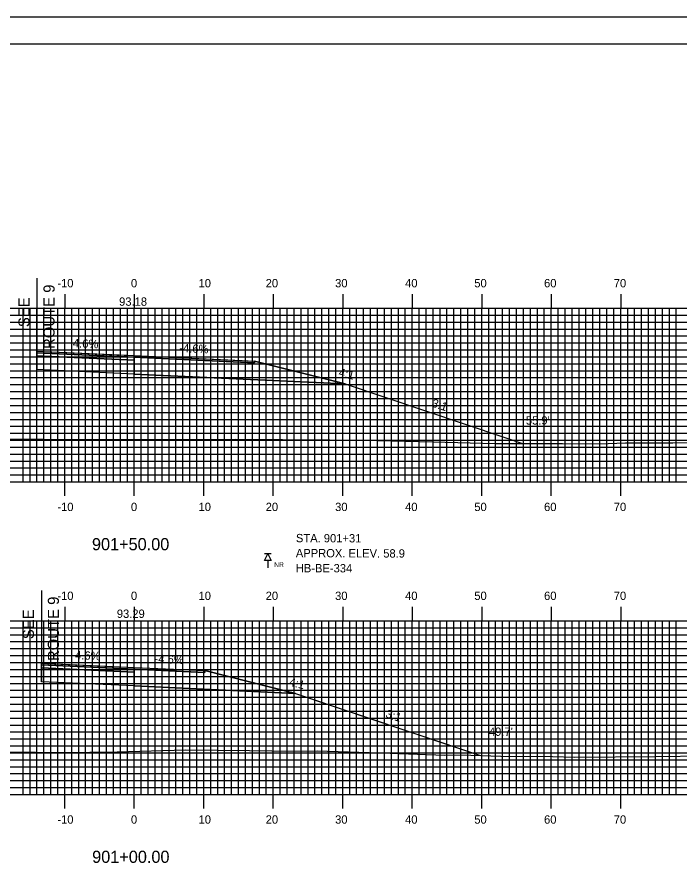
# Model space of a CAD drawing. Extents: x 856323 to 856666, y 364765 to 364985.
# Drawn here: x 856471.9 to 856567.3, y 364861.3 to 364985.2 of the extents above; entities that cross this region are included whole.
import ezdxf

# ---------------------------------------------------------------- set-up
doc = ezdxf.new("R2010")
doc.units = 0
for name, color, linetype in [('ANNOTATION', 7, 'Continuous'), ('BORDER', 7, 'Continuous'), ('BORING - NO REFUSAL', 7, 'Continuous'), ('D_Roadway_Centerline', 7, 'Continuous'), ('D_Roadway_Centerline_Text', 7, 'Continuous'), ('D_Roadway_Edge_Shoulder', 7, 'Continuous'), ('D_Roadway_Edge_TW', 7, 'Continuous'), ('D_Roadway_Pavement', 7, 'Continuous'), ('D_Roadway_SlopeLines', 7, 'Continuous'), ('D_Roadway_SubGrade', 7, 'Continuous'), ('D_Text_Standard', 7, 'Continuous'), ('H_V ANNOTATION', 7, 'Continuous'), ('MAJOR', 7, 'Continuous'), ('MINOR', 7, 'Continuous'), ('PLOT BOUNDARY', 7, 'Continuous'), ('S_Roadway_Centerline', 7, 'Continuous')]:
    doc.layers.add(name, color=color, linetype=linetype)

msp = doc.modelspace()

# ---------------------------------------------------------------- linework, layer by layer
at = {"layer": 'BORDER'}
msp.add_lwpolyline([(856339.17, 364771.3), (856659.17, 364771.3), (856659.17, 364981.3), (856339.17, 364981.3)], close=True, dxfattribs=at)
at = {"layer": 'BORING - NO REFUSAL'}
for p, q in [((856508.45, 364907.96), (856507.49, 364907.96)), ((856507.97, 364907), (856507.97, 364905.94))]:
    msp.add_line(p, q, dxfattribs=at)
msp.add_lwpolyline([(856507.97, 364907.96), (856508.45, 364907), (856507.49, 364907)], close=True, dxfattribs=at)
at = {"layer": 'D_Roadway_Centerline'}
for points in [[(856474.77, 364937.13), (856487.33, 364936.55), (856488.77, 364936.48), (856504.31, 364935.77), (856506.05, 364935.69), (856516.85, 364932.99), (856518.05, 364932.69), (856519.01, 364932.45), (856519.12, 364932.42), (856542.07, 364924.69), (856544.62, 364923.83)], [(856475.4, 364892.21), (856478.19, 364892.08), (856488.77, 364891.59), (856493.27, 364891.39), (856498.91, 364891.13), (856504.25, 364889.79), (856510.91, 364888.13), (856511.39, 364888.01), (856511.99, 364887.86), (856523.83, 364883.87), (856538.47, 364878.94)]]:
    msp.add_lwpolyline(points, dxfattribs=at)
at = {"layer": 'D_Roadway_Edge_Shoulder'}
for points in [[(856488.77, 364936.48), (856506.05, 364935.69), (856506.05, 364935.44), (856488.77, 364936.23)], [(856488.77, 364891.59), (856498.91, 364891.13), (856498.91, 364890.88), (856488.77, 364891.34)]]:
    msp.add_lwpolyline(points, close=True, dxfattribs=at)
at = {"layer": 'D_Roadway_Edge_TW'}
for points in [[(856474.77, 364937.13), (856488.77, 364936.48), (856488.77, 364936.23), (856474.77, 364936.88)], [(856474.77, 364937.13), (856488.77, 364936.48), (856488.77, 364936.23), (856474.77, 364936.88)], [(856474.77, 364937.13), (856488.77, 364936.48), (856488.77, 364936.23), (856474.77, 364936.88)], [(856475.4, 364892.21), (856488.77, 364891.59), (856488.77, 364891.34), (856475.4, 364891.96)], [(856475.4, 364892.21), (856488.77, 364891.59), (856488.77, 364891.34), (856475.4, 364891.96)]]:
    msp.add_lwpolyline(points, close=True, dxfattribs=at)
for points in [[(856474.77, 364937.13), (856474.77, 364936.88)], [(856474.77, 364937.13), (856474.77, 364936.88)], [(856475.4, 364892.21), (856475.4, 364891.96)], [(856475.4, 364892.21), (856475.4, 364891.96)], [(856475.4, 364892.21), (856488.77, 364891.59), (856488.77, 364891.34), (856475.4, 364891.96)]]:
    msp.add_lwpolyline(points, dxfattribs=at)
at = {"layer": 'D_Roadway_Pavement'}
for points in [[(856474.77, 364936.88), (856488.77, 364936.23), (856488.77, 364935.82), (856474.77, 364936.46)], [(856474.77, 364936.88), (856488.77, 364936.23), (856488.77, 364935.82), (856474.77, 364936.46)], [(856474.77, 364936.88), (856488.77, 364936.23), (856488.77, 364935.82), (856474.77, 364936.46)], [(856474.77, 364936.88), (856488.77, 364936.23), (856488.77, 364935.82), (856474.77, 364936.46)], [(856475.4, 364891.96), (856488.77, 364891.34), (856488.77, 364890.93), (856475.4, 364891.54)], [(856475.4, 364891.96), (856488.77, 364891.34), (856488.77, 364890.93), (856475.4, 364891.54)], [(856475.4, 364891.96), (856488.77, 364891.34), (856488.77, 364890.93), (856475.4, 364891.54)], [(856475.4, 364891.96), (856488.77, 364891.34), (856488.77, 364890.93), (856475.4, 364891.54)]]:
    msp.add_lwpolyline(points, close=True, dxfattribs=at)
for points in [[(856474.77, 364936.88), (856474.77, 364936.46)], [(856474.77, 364936.88), (856474.77, 364936.46)], [(856474.77, 364936.88), (856474.77, 364936.46)], [(856474.77, 364936.88), (856474.77, 364936.46)], [(856488.77, 364936.23), (856488.77, 364935.82)], [(856488.77, 364936.23), (856488.77, 364935.82)], [(856488.77, 364936.23), (856488.77, 364935.82)], [(856488.77, 364936.23), (856488.77, 364935.82)], [(856488.77, 364936.23), (856488.77, 364935.82)], [(856488.77, 364936.23), (856488.77, 364935.82)], [(856488.77, 364936.23), (856488.77, 364935.82)], [(856488.77, 364936.23), (856488.77, 364935.82)], [(856475.4, 364891.96), (856475.4, 364891.54)], [(856475.4, 364891.96), (856475.4, 364891.54)], [(856475.4, 364891.96), (856475.4, 364891.54)], [(856475.4, 364891.96), (856475.4, 364891.54)], [(856488.77, 364891.34), (856488.77, 364890.93)], [(856488.77, 364891.34), (856488.77, 364890.93)], [(856488.77, 364891.34), (856488.77, 364890.93)], [(856488.77, 364891.34), (856488.77, 364890.93)], [(856488.77, 364891.34), (856488.77, 364890.93)], [(856488.77, 364891.34), (856488.77, 364890.93)], [(856488.77, 364891.34), (856488.77, 364890.93)], [(856488.77, 364891.34), (856488.77, 364890.93)]]:
    msp.add_lwpolyline(points, dxfattribs=at)
at = {"layer": 'D_Roadway_SlopeLines'}
msp.add_lwpolyline([(856498.91, 364891.13), (856511.99, 364887.86), (856538.47, 364878.94)], dxfattribs=at)
at = {"layer": 'D_Roadway_SubGrade'}
for p, q in [((856474.77, 364947.6), (856474.77, 364934.46)), ((856475.4, 364902.68), (856475.4, 364889.54))]:
    msp.add_line(p, q, dxfattribs=at)
for points in [[(856474.77, 364936.46), (856488.77, 364935.82), (856488.77, 364933.82), (856474.77, 364934.46)], [(856474.77, 364936.46), (856488.77, 364935.82), (856488.77, 364933.82), (856474.77, 364934.46)], [(856488.77, 364935.82), (856488.77, 364936.23), (856506.05, 364935.44), (856506.05, 364935.69), (856519.12, 364932.42), (856488.77, 364933.82)], [(856488.77, 364933.82), (856519.12, 364932.42), (856506.05, 364935.69), (856506.05, 364935.44), (856488.77, 364936.23), (856488.77, 364935.82)], [(856488.77, 364935.82), (856488.77, 364936.23), (856506.05, 364935.44), (856506.05, 364935.69), (856519.12, 364932.42), (856488.77, 364933.82)], [(856475.4, 364891.54), (856488.77, 364890.93), (856488.77, 364888.93), (856475.4, 364889.54)], [(856475.4, 364891.54), (856488.77, 364890.93), (856488.77, 364888.93), (856475.4, 364889.54)], [(856488.77, 364890.93), (856488.77, 364891.34), (856498.91, 364890.88), (856498.91, 364891.13), (856511.99, 364887.86), (856488.77, 364888.93)], [(856488.77, 364888.93), (856511.99, 364887.86), (856498.91, 364891.13), (856498.91, 364890.88), (856488.77, 364891.34), (856488.77, 364890.93)], [(856488.77, 364890.93), (856488.77, 364891.34), (856498.91, 364890.88), (856498.91, 364891.13), (856511.99, 364887.86), (856488.77, 364888.93)]]:
    msp.add_lwpolyline(points, close=True, dxfattribs=at)
for points in [[(856474.77, 364936.46), (856474.77, 364934.46)], [(856474.77, 364936.46), (856474.77, 364934.46)], [(856475.4, 364891.54), (856475.4, 364889.54)], [(856475.4, 364891.54), (856475.4, 364889.54)]]:
    msp.add_lwpolyline(points, dxfattribs=at)
at = {"layer": 'MAJOR'}
for p, q in [((856478.77, 364945.31), (856478.77, 364943.3)), ((856488.77, 364945.31), (856488.77, 364943.3)), ((856498.77, 364945.31), (856498.77, 364943.3)), ((856508.77, 364945.31), (856508.77, 364943.3)), ((856518.77, 364945.31), (856518.77, 364943.3)), ((856528.77, 364945.31), (856528.77, 364943.3)), ((856538.77, 364945.31), (856538.77, 364943.3)), ((856548.77, 364945.31), (856548.77, 364943.3)), ((856558.77, 364945.31), (856558.77, 364943.3)), ((856348.77, 364943.3), (856628.77, 364943.3)), ((856348.77, 364943.3), (856628.77, 364943.3)), ((856478.77, 364918.3), (856478.77, 364943.3)), ((856488.77, 364918.3), (856488.77, 364943.3)), ((856498.77, 364918.3), (856498.77, 364943.3)), ((856508.77, 364918.3), (856508.77, 364943.3)), ((856518.77, 364918.3), (856518.77, 364943.3)), ((856528.77, 364918.3), (856528.77, 364943.3)), ((856538.77, 364918.3), (856538.77, 364943.3)), ((856548.77, 364918.3), (856548.77, 364943.3)), ((856558.77, 364918.3), (856558.77, 364943.3)), ((856348.77, 364938.3), (856628.77, 364938.3)), ((856348.77, 364933.3), (856628.77, 364933.3)), ((856348.77, 364928.3), (856628.77, 364928.3)), ((856348.77, 364923.3), (856628.77, 364923.3)), ((856348.77, 364918.3), (856628.77, 364918.3)), ((856348.77, 364918.3), (856628.77, 364918.3)), ((856478.77, 364916.3), (856478.77, 364918.3)), ((856488.77, 364916.3), (856488.77, 364918.3)), ((856498.77, 364916.3), (856498.77, 364918.3)), ((856508.77, 364916.3), (856508.77, 364918.3)), ((856518.77, 364916.3), (856518.77, 364918.3)), ((856528.77, 364916.3), (856528.77, 364918.3)), ((856538.77, 364916.3), (856538.77, 364918.3)), ((856548.77, 364916.3), (856548.77, 364918.3)), ((856558.77, 364916.3), (856558.77, 364918.3)), ((856478.77, 364900.31), (856478.77, 364898.3)), ((856488.77, 364900.31), (856488.77, 364898.3)), ((856498.77, 364900.31), (856498.77, 364898.3)), ((856508.77, 364900.31), (856508.77, 364898.3)), ((856518.77, 364900.31), (856518.77, 364898.3)), ((856528.77, 364900.31), (856528.77, 364898.3)), ((856538.77, 364900.31), (856538.77, 364898.3)), ((856548.77, 364900.31), (856548.77, 364898.3)), ((856558.77, 364900.31), (856558.77, 364898.3)), ((856348.77, 364898.3), (856628.77, 364898.3)), ((856348.77, 364898.3), (856628.77, 364898.3)), ((856478.77, 364873.3), (856478.77, 364898.3)), ((856488.77, 364873.3), (856488.77, 364898.3)), ((856498.77, 364873.3), (856498.77, 364898.3)), ((856508.77, 364873.3), (856508.77, 364898.3)), ((856518.77, 364873.3), (856518.77, 364898.3)), ((856528.77, 364873.3), (856528.77, 364898.3)), ((856538.77, 364873.3), (856538.77, 364898.3)), ((856548.77, 364873.3), (856548.77, 364898.3)), ((856558.77, 364873.3), (856558.77, 364898.3)), ((856348.77, 364893.3), (856628.77, 364893.3)), ((856348.77, 364888.3), (856628.77, 364888.3)), ((856348.77, 364883.3), (856628.77, 364883.3)), ((856348.77, 364878.3), (856628.77, 364878.3)), ((856348.77, 364873.3), (856628.77, 364873.3)), ((856348.77, 364873.3), (856628.77, 364873.3)), ((856478.77, 364871.3), (856478.77, 364873.3)), ((856488.77, 364871.3), (856488.77, 364873.3)), ((856498.77, 364871.3), (856498.77, 364873.3)), ((856508.77, 364871.3), (856508.77, 364873.3)), ((856518.77, 364871.3), (856518.77, 364873.3)), ((856528.77, 364871.3), (856528.77, 364873.3)), ((856538.77, 364871.3), (856538.77, 364873.3)), ((856548.77, 364871.3), (856548.77, 364873.3)), ((856558.77, 364871.3), (856558.77, 364873.3))]:
    msp.add_line(p, q, dxfattribs=at)
at = {"layer": 'MINOR'}
for p, q in [((856472.77, 364918.3), (856472.77, 364943.3)), ((856473.77, 364918.3), (856473.77, 364943.3)), ((856474.77, 364918.3), (856474.77, 364943.3)), ((856475.77, 364918.3), (856475.77, 364943.3)), ((856476.77, 364918.3), (856476.77, 364943.3)), ((856477.77, 364918.3), (856477.77, 364943.3)), ((856479.77, 364918.3), (856479.77, 364943.3)), ((856480.77, 364918.3), (856480.77, 364943.3)), ((856481.77, 364918.3), (856481.77, 364943.3)), ((856482.77, 364918.3), (856482.77, 364943.3)), ((856483.77, 364918.3), (856483.77, 364943.3)), ((856484.77, 364918.3), (856484.77, 364943.3)), ((856485.77, 364918.3), (856485.77, 364943.3)), ((856486.77, 364918.3), (856486.77, 364943.3)), ((856487.77, 364918.3), (856487.77, 364943.3)), ((856489.77, 364918.3), (856489.77, 364943.3)), ((856490.77, 364918.3), (856490.77, 364943.3)), ((856491.77, 364918.3), (856491.77, 364943.3)), ((856492.77, 364918.3), (856492.77, 364943.3)), ((856493.77, 364918.3), (856493.77, 364943.3)), ((856494.77, 364918.3), (856494.77, 364943.3)), ((856495.77, 364918.3), (856495.77, 364943.3)), ((856496.77, 364918.3), (856496.77, 364943.3)), ((856497.77, 364918.3), (856497.77, 364943.3)), ((856499.77, 364918.3), (856499.77, 364943.3)), ((856500.77, 364918.3), (856500.77, 364943.3)), ((856501.77, 364918.3), (856501.77, 364943.3)), ((856502.77, 364918.3), (856502.77, 364943.3)), ((856503.77, 364918.3), (856503.77, 364943.3)), ((856504.77, 364918.3), (856504.77, 364943.3)), ((856505.77, 364918.3), (856505.77, 364943.3)), ((856506.77, 364918.3), (856506.77, 364943.3)), ((856507.77, 364918.3), (856507.77, 364943.3)), ((856509.77, 364918.3), (856509.77, 364943.3)), ((856510.77, 364918.3), (856510.77, 364943.3)), ((856511.77, 364918.3), (856511.77, 364943.3)), ((856512.77, 364918.3), (856512.77, 364943.3)), ((856513.77, 364918.3), (856513.77, 364943.3)), ((856514.77, 364918.3), (856514.77, 364943.3)), ((856515.77, 364918.3), (856515.77, 364943.3)), ((856516.77, 364918.3), (856516.77, 364943.3)), ((856517.77, 364918.3), (856517.77, 364943.3)), ((856519.77, 364918.3), (856519.77, 364943.3)), ((856520.77, 364918.3), (856520.77, 364943.3)), ((856521.77, 364918.3), (856521.77, 364943.3)), ((856522.77, 364918.3), (856522.77, 364943.3)), ((856523.77, 364918.3), (856523.77, 364943.3)), ((856524.77, 364918.3), (856524.77, 364943.3)), ((856525.77, 364918.3), (856525.77, 364943.3)), ((856526.77, 364918.3), (856526.77, 364943.3)), ((856527.77, 364918.3), (856527.77, 364943.3)), ((856529.77, 364918.3), (856529.77, 364943.3)), ((856530.77, 364918.3), (856530.77, 364943.3)), ((856531.77, 364918.3), (856531.77, 364943.3)), ((856532.77, 364918.3), (856532.77, 364943.3)), ((856533.77, 364918.3), (856533.77, 364943.3)), ((856534.77, 364918.3), (856534.77, 364943.3)), ((856535.77, 364918.3), (856535.77, 364943.3)), ((856536.77, 364918.3), (856536.77, 364943.3)), ((856537.77, 364918.3), (856537.77, 364943.3)), ((856539.77, 364918.3), (856539.77, 364943.3)), ((856540.77, 364918.3), (856540.77, 364943.3)), ((856541.77, 364918.3), (856541.77, 364943.3)), ((856542.77, 364918.3), (856542.77, 364943.3)), ((856543.77, 364918.3), (856543.77, 364943.3)), ((856544.77, 364918.3), (856544.77, 364943.3)), ((856545.77, 364918.3), (856545.77, 364943.3)), ((856546.77, 364918.3), (856546.77, 364943.3)), ((856547.77, 364918.3), (856547.77, 364943.3)), ((856549.77, 364918.3), (856549.77, 364943.3)), ((856550.77, 364918.3), (856550.77, 364943.3)), ((856551.77, 364918.3), (856551.77, 364943.3)), ((856552.77, 364918.3), (856552.77, 364943.3)), ((856553.77, 364918.3), (856553.77, 364943.3)), ((856554.77, 364918.3), (856554.77, 364943.3)), ((856555.77, 364918.3), (856555.77, 364943.3)), ((856556.77, 364918.3), (856556.77, 364943.3)), ((856557.77, 364918.3), (856557.77, 364943.3)), ((856559.77, 364918.3), (856559.77, 364943.3)), ((856560.77, 364918.3), (856560.77, 364943.3)), ((856561.77, 364918.3), (856561.77, 364943.3)), ((856562.77, 364918.3), (856562.77, 364943.3)), ((856563.77, 364918.3), (856563.77, 364943.3)), ((856564.77, 364918.3), (856564.77, 364943.3)), ((856565.77, 364918.3), (856565.77, 364943.3)), ((856566.77, 364918.3), (856566.77, 364943.3)), ((856348.77, 364942.3), (856628.77, 364942.3)), ((856348.77, 364941.3), (856628.77, 364941.3)), ((856348.77, 364940.3), (856628.77, 364940.3)), ((856348.77, 364939.3), (856628.77, 364939.3)), ((856348.77, 364937.3), (856628.77, 364937.3)), ((856348.77, 364936.3), (856628.77, 364936.3)), ((856348.77, 364935.3), (856628.77, 364935.3)), ((856348.77, 364934.3), (856628.77, 364934.3)), ((856348.77, 364932.3), (856628.77, 364932.3)), ((856348.77, 364931.3), (856628.77, 364931.3)), ((856348.77, 364930.3), (856628.77, 364930.3)), ((856348.77, 364929.3), (856628.77, 364929.3)), ((856348.77, 364927.3), (856628.77, 364927.3)), ((856348.77, 364926.3), (856628.77, 364926.3)), ((856348.77, 364925.3), (856628.77, 364925.3)), ((856348.77, 364924.3), (856628.77, 364924.3)), ((856348.77, 364922.3), (856628.77, 364922.3)), ((856348.77, 364921.3), (856628.77, 364921.3)), ((856348.77, 364920.3), (856628.77, 364920.3)), ((856348.77, 364919.3), (856628.77, 364919.3)), ((856348.77, 364897.3), (856628.77, 364897.3)), ((856472.77, 364873.3), (856472.77, 364898.3)), ((856473.77, 364873.3), (856473.77, 364898.3)), ((856474.77, 364873.3), (856474.77, 364898.3)), ((856475.77, 364873.3), (856475.77, 364898.3)), ((856476.77, 364873.3), (856476.77, 364898.3)), ((856477.77, 364873.3), (856477.77, 364898.3)), ((856479.77, 364873.3), (856479.77, 364898.3)), ((856480.77, 364873.3), (856480.77, 364898.3)), ((856481.77, 364873.3), (856481.77, 364898.3)), ((856482.77, 364873.3), (856482.77, 364898.3)), ((856483.77, 364873.3), (856483.77, 364898.3)), ((856484.77, 364873.3), (856484.77, 364898.3)), ((856485.77, 364873.3), (856485.77, 364898.3)), ((856486.77, 364873.3), (856486.77, 364898.3)), ((856487.77, 364873.3), (856487.77, 364898.3)), ((856489.77, 364873.3), (856489.77, 364898.3)), ((856490.77, 364873.3), (856490.77, 364898.3)), ((856491.77, 364873.3), (856491.77, 364898.3)), ((856492.77, 364873.3), (856492.77, 364898.3)), ((856493.77, 364873.3), (856493.77, 364898.3)), ((856494.77, 364873.3), (856494.77, 364898.3)), ((856495.77, 364873.3), (856495.77, 364898.3)), ((856496.77, 364873.3), (856496.77, 364898.3)), ((856497.77, 364873.3), (856497.77, 364898.3)), ((856499.77, 364873.3), (856499.77, 364898.3)), ((856500.77, 364873.3), (856500.77, 364898.3)), ((856501.77, 364873.3), (856501.77, 364898.3)), ((856502.77, 364873.3), (856502.77, 364898.3)), ((856503.77, 364873.3), (856503.77, 364898.3)), ((856504.77, 364873.3), (856504.77, 364898.3)), ((856505.77, 364873.3), (856505.77, 364898.3)), ((856506.77, 364873.3), (856506.77, 364898.3)), ((856507.77, 364873.3), (856507.77, 364898.3)), ((856509.77, 364873.3), (856509.77, 364898.3)), ((856510.77, 364873.3), (856510.77, 364898.3)), ((856511.77, 364873.3), (856511.77, 364898.3)), ((856512.77, 364873.3), (856512.77, 364898.3)), ((856513.77, 364873.3), (856513.77, 364898.3)), ((856514.77, 364873.3), (856514.77, 364898.3)), ((856515.77, 364873.3), (856515.77, 364898.3)), ((856516.77, 364873.3), (856516.77, 364898.3)), ((856517.77, 364873.3), (856517.77, 364898.3)), ((856519.77, 364873.3), (856519.77, 364898.3)), ((856520.77, 364873.3), (856520.77, 364898.3)), ((856521.77, 364873.3), (856521.77, 364898.3)), ((856522.77, 364873.3), (856522.77, 364898.3)), ((856523.77, 364873.3), (856523.77, 364898.3)), ((856524.77, 364873.3), (856524.77, 364898.3)), ((856525.77, 364873.3), (856525.77, 364898.3)), ((856526.77, 364873.3), (856526.77, 364898.3)), ((856527.77, 364873.3), (856527.77, 364898.3)), ((856529.77, 364873.3), (856529.77, 364898.3)), ((856530.77, 364873.3), (856530.77, 364898.3)), ((856531.77, 364873.3), (856531.77, 364898.3)), ((856532.77, 364873.3), (856532.77, 364898.3)), ((856533.77, 364873.3), (856533.77, 364898.3)), ((856534.77, 364873.3), (856534.77, 364898.3)), ((856535.77, 364873.3), (856535.77, 364898.3)), ((856536.77, 364873.3), (856536.77, 364898.3)), ((856537.77, 364873.3), (856537.77, 364898.3)), ((856539.77, 364873.3), (856539.77, 364898.3)), ((856540.77, 364873.3), (856540.77, 364898.3)), ((856541.77, 364873.3), (856541.77, 364898.3)), ((856542.77, 364873.3), (856542.77, 364898.3)), ((856543.77, 364873.3), (856543.77, 364898.3)), ((856544.77, 364873.3), (856544.77, 364898.3)), ((856545.77, 364873.3), (856545.77, 364898.3)), ((856546.77, 364873.3), (856546.77, 364898.3)), ((856547.77, 364873.3), (856547.77, 364898.3)), ((856549.77, 364873.3), (856549.77, 364898.3)), ((856550.77, 364873.3), (856550.77, 364898.3)), ((856551.77, 364873.3), (856551.77, 364898.3)), ((856552.77, 364873.3), (856552.77, 364898.3)), ((856553.77, 364873.3), (856553.77, 364898.3)), ((856554.77, 364873.3), (856554.77, 364898.3)), ((856555.77, 364873.3), (856555.77, 364898.3)), ((856556.77, 364873.3), (856556.77, 364898.3)), ((856557.77, 364873.3), (856557.77, 364898.3)), ((856559.77, 364873.3), (856559.77, 364898.3)), ((856560.77, 364873.3), (856560.77, 364898.3)), ((856561.77, 364873.3), (856561.77, 364898.3)), ((856562.77, 364873.3), (856562.77, 364898.3)), ((856563.77, 364873.3), (856563.77, 364898.3)), ((856564.77, 364873.3), (856564.77, 364898.3)), ((856565.77, 364873.3), (856565.77, 364898.3)), ((856566.77, 364873.3), (856566.77, 364898.3)), ((856348.77, 364896.3), (856628.77, 364896.3)), ((856348.77, 364895.3), (856628.77, 364895.3)), ((856348.77, 364894.3), (856628.77, 364894.3)), ((856348.77, 364892.3), (856628.77, 364892.3)), ((856348.77, 364891.3), (856628.77, 364891.3)), ((856348.77, 364890.3), (856628.77, 364890.3)), ((856348.77, 364889.3), (856628.77, 364889.3)), ((856348.77, 364887.3), (856628.77, 364887.3)), ((856348.77, 364886.3), (856628.77, 364886.3)), ((856348.77, 364885.3), (856628.77, 364885.3)), ((856348.77, 364884.3), (856628.77, 364884.3)), ((856348.77, 364882.3), (856628.77, 364882.3)), ((856348.77, 364881.3), (856628.77, 364881.3)), ((856348.77, 364880.3), (856628.77, 364880.3)), ((856348.77, 364879.3), (856628.77, 364879.3)), ((856348.77, 364877.3), (856628.77, 364877.3)), ((856348.77, 364876.3), (856628.77, 364876.3)), ((856348.77, 364875.3), (856628.77, 364875.3)), ((856348.77, 364874.3), (856628.77, 364874.3))]:
    msp.add_line(p, q, dxfattribs=at)
at = {"layer": 'PLOT BOUNDARY'}
msp.add_lwpolyline([(856322.98, 364765.18), (856662.98, 364765.18), (856662.98, 364985.18), (856322.98, 364985.18)], close=True, dxfattribs=at)
at = {"layer": 'S_Roadway_Centerline'}
for points in [[(856469.99, 364924.48), (856481.66, 364924.38), (856483.59, 364924.39), (856484.17, 364924.38), (856486.38, 364924.39), (856503.32, 364924.46), (856516.92, 364924.34), (856521.76, 364924.3), (856531.69, 364924.06), (856540.75, 364923.82), (856544.17, 364923.83), (856550.39, 364923.82), (856555.71, 364923.79), (856559.44, 364923.93), (856566.27, 364923.94), (856576.82, 364924.1), (856581.11, 364923.92), (856590.28, 364924.07), (856594.86, 364924.09), (856605.52, 364923.7), (856614.14, 364923.57), (856622.01, 364923.48), (856628.77, 364923.69)], [(856470.76, 364879.44), (856478.38, 364879.33), (856486.33, 364879.45), (856496.15, 364879.71), (856505.33, 364879.61), (856511.77, 364879.53), (856515.07, 364879.59), (856525.6, 364879.25), (856533.48, 364878.95), (856535.78, 364879.03), (856541.53, 364878.84), (856548.97, 364878.79), (856552.15, 364878.69), (856563.84, 364878.75), (856570.89, 364878.85)]]:
    msp.add_lwpolyline(points, dxfattribs=at)

# ---------------------------------------------------------------- texts
at = {"layer": 'ANNOTATION'}
for s, height, rotation, p in [('ROUTE 9', 1.6, 90, (856477.3, 364937.43)), ('SEE', 1.6, 90, (856473.7, 364940.58)), ('4.6%', 1.2, 357.3662, (856479.92, 364937.69)), ('-4.6%', 1.2, 357.3663, (856495.23, 364936.99)), ('4:1', 1.2, 345.9638, (856518.09, 364933.54)), ('3:1', 1.2, 341.3848, (856531.48, 364929.17)), ('ROUTE 9', 1.6, 90, (856477.93, 364892.51)), ('SEE', 1.6, 90, (856474.33, 364895.66)), ('4.6%', 1.2, 357.3694, (856480.23, 364892.79)), ('-4.6%', 1.2, 357.3663, (856491.67, 364892.26)), ('4:1', 1.2, 345.9638, (856510.96, 364888.98)), ('3:1', 1.2, 341.3915, (856524.84, 364884.44))]:
    msp.add_text(s, height=height, rotation=rotation, dxfattribs=at).set_placement(p)
at = {"layer": 'BORING - NO REFUSAL'}
for s, p in [('STA. 901+31', (856512.03, 364909.61)), ('APPROX. ELEV. 58.9', (856512.02, 364907.45)), ('HB-BE-334', (856512.01, 364905.29))]:
    msp.add_text(s, height=1.2, rotation=359.8142, dxfattribs=at).set_placement(p)
msp.add_text('NR', height=0.7, dxfattribs=at).set_placement((856508.9, 364906.04))
at = {"layer": 'D_Roadway_Centerline_Text'}
for s, p in [('93.18', (856486.59, 364943.65)), ('93.29', (856486.26, 364898.72))]:
    msp.add_text(s, height=1.2, dxfattribs=at).set_placement(p)
at = {"layer": 'D_Text_Standard'}
for s, p in [("55.9'", (856545.12, 364926.55)), ("49.7'", (856539.81, 364881.74))]:
    msp.add_text(s, height=1.2, dxfattribs=at).set_placement(p)
at = {"layer": 'H_V ANNOTATION'}
for s, height, p in [('-10', 1.2, (856477.7, 364946.3)), ('0', 1.2, (856488.29, 364946.3)), ('10', 1.2, (856498.02, 364946.3)), ('20', 1.2, (856507.68, 364946.3)), ('30', 1.2, (856517.67, 364946.3)), ('40', 1.2, (856527.74, 364946.3)), ('50', 1.2, (856537.7, 364946.3)), ('60', 1.2, (856547.74, 364946.3)), ('70', 1.2, (856557.77, 364946.3)), ('-10', 1.2, (856477.7, 364914.1)), ('0', 1.2, (856488.29, 364914.1)), ('10', 1.2, (856498.02, 364914.1)), ('20', 1.2, (856507.68, 364914.1)), ('30', 1.2, (856517.67, 364914.1)), ('40', 1.2, (856527.74, 364914.1)), ('50', 1.2, (856537.7, 364914.1)), ('60', 1.2, (856547.74, 364914.1)), ('70', 1.2, (856557.77, 364914.1)), ('901+50.00', 1.75, (856482.68, 364908.46)), ('-10', 1.2, (856477.7, 364901.3)), ('0', 1.2, (856488.29, 364901.3)), ('10', 1.2, (856498.02, 364901.3)), ('20', 1.2, (856507.68, 364901.3)), ('30', 1.2, (856517.67, 364901.3)), ('40', 1.2, (856527.74, 364901.3)), ('50', 1.2, (856537.7, 364901.3)), ('60', 1.2, (856547.74, 364901.3)), ('70', 1.2, (856557.77, 364901.3)), ('-10', 1.2, (856477.7, 364869.1)), ('0', 1.2, (856488.29, 364869.1)), ('10', 1.2, (856498.02, 364869.1)), ('20', 1.2, (856507.68, 364869.1)), ('30', 1.2, (856517.67, 364869.1)), ('40', 1.2, (856527.74, 364869.1)), ('50', 1.2, (856537.7, 364869.1)), ('60', 1.2, (856547.74, 364869.1)), ('70', 1.2, (856557.77, 364869.1)), ('901+00.00', 1.75, (856482.71, 364863.46))]:
    msp.add_text(s, height=height, dxfattribs=at).set_placement(p)

doc.saveas('drawing.dxf')
